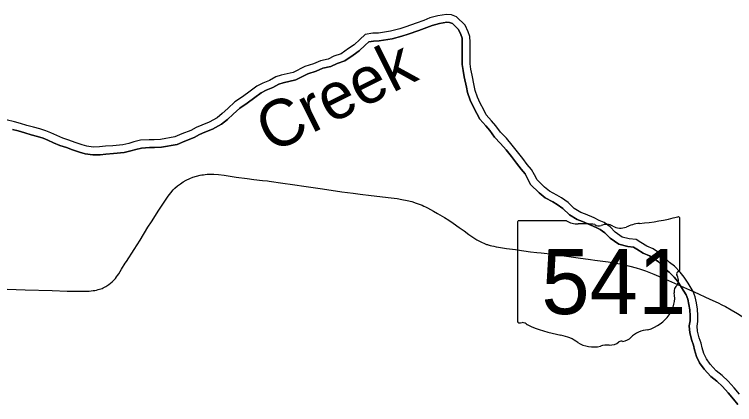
# Model space of a CAD drawing. Extents: x -29.6 to 34, y 0 to 22.
# Drawn here: x -24.702 to -23.331, y 11.058 to 11.8 of the extents above; entities that cross this region are included whole.
import ezdxf

# ---------------------------------------------------------------- set-up
doc = ezdxf.new("R2010")
doc.units = 0
for name, color, linetype in [('GM_X_County_Road', 7, 'Continuous'), ('GM_X_Major_River', 7, 'Continuous'), ('GM_X_Major_River_Text', 7, 'Continuous'), ('GM_X_State_Route', 7, 'Continuous'), ('GM_X_State_Shield', 7, 'Continuous')]:
    doc.layers.add(name, color=color, linetype=linetype)

msp = doc.modelspace()

# ---------------------------------------------------------------- linework, layer by layer
at = {"layer": 'GM_X_County_Road'}
for points in [[(-23.7078, 11.3472), (-23.6991, 11.3463), (-23.6771, 11.3437), (-23.6724, 11.3432)], [(-23.6724, 11.3432), (-23.6644, 11.3423), (-23.6376, 11.3385)], [(-23.6376, 11.3385), (-23.6287, 11.3372), (-23.6056, 11.3338), (-23.5973, 11.3326)], [(-23.5973, 11.3326), (-23.5722, 11.3292), (-23.5566, 11.3268), (-23.5435, 11.3242), (-23.5304, 11.3213), (-23.5185, 11.3182), (-23.5101, 11.3155), (-23.5008, 11.3122), (-23.4851, 11.3059), (-23.4719, 11.3003)], [(-23.4719, 11.3003), (-23.4631, 11.2965), (-23.4232, 11.2787), (-23.417, 11.2758), (-23.4086, 11.2721), (-23.3783, 11.2586), (-23.3627, 11.2513), (-23.3556, 11.2478)]]:
    msp.add_lwpolyline(points, dxfattribs=at)
at = {"layer": 'GM_X_Major_River'}
for points in [[(-23.8088, 11.6188), (-23.8157, 11.6316), (-23.8207, 11.6426), (-23.8251, 11.6553), (-23.8269, 11.6649), (-23.831, 11.6844), (-23.8332, 11.6958), (-23.8347, 11.7061), (-23.8348, 11.716), (-23.8345, 11.7267), (-23.8347, 11.7477), (-23.8352, 11.758), (-23.8384, 11.7672), (-23.8439, 11.78), (-23.8603, 11.7958), (-23.8703, 11.7993), (-23.8795, 11.8003), (-23.8962, 11.7973), (-23.9114, 11.7937), (-23.9224, 11.789), (-23.9373, 11.7835), (-23.9571, 11.7766), (-23.9684, 11.773), (-23.9858, 11.7682), (-24.0092, 11.7648), (-24.0198, 11.7644), (-24.034, 11.7621), (-24.0442, 11.7528), (-24.0551, 11.7424), (-24.0657, 11.7352), (-24.0799, 11.7255), (-24.0937, 11.7208), (-24.1046, 11.715), (-24.1192, 11.7121), (-24.1326, 11.7063), (-24.1489, 11.7012), (-24.1715, 11.69), (-24.1942, 11.6845), (-24.2041, 11.6812), (-24.2165, 11.6747), (-24.2289, 11.6693), (-24.2402, 11.6635), (-24.2529, 11.6541), (-24.2674, 11.6437), (-24.2822, 11.6337), (-24.2956, 11.6211), (-24.3061, 11.6114), (-24.3157, 11.6035), (-24.3309, 11.5952), (-24.345, 11.5898), (-24.356, 11.5851), (-24.3659, 11.5793), (-24.3829, 11.5728), (-24.3963, 11.567), (-24.4236, 11.5622), (-24.4357, 11.5617), (-24.4453, 11.5616), (-24.4619, 11.5608), (-24.4747, 11.5575), (-24.4839, 11.5549), (-24.4956, 11.552), (-24.5144, 11.5501), (-24.5286, 11.5493), (-24.5396, 11.5481), (-24.5517, 11.5477), (-24.5641, 11.5493), (-24.573, 11.5521), (-24.5862, 11.5566), (-24.5979, 11.5608), (-24.6097, 11.5646), (-24.6211, 11.5695), (-24.6321, 11.5748), (-24.6417, 11.5786), (-24.6535, 11.5825), (-24.6656, 11.5856), (-24.6777, 11.589), (-24.6901, 11.5928), (-24.7015, 11.596), (-24.7172, 11.5997)], [(-23.8219, 11.6118), (-23.829, 11.6249), (-23.8346, 11.637), (-23.8395, 11.6515), (-23.8415, 11.662), (-23.8456, 11.6815), (-23.8479, 11.6933), (-23.8496, 11.705), (-23.8497, 11.7162), (-23.8494, 11.7268), (-23.8496, 11.7473), (-23.8499, 11.7551), (-23.8523, 11.7618), (-23.8564, 11.7714), (-23.8683, 11.7829), (-23.8736, 11.7847), (-23.879, 11.7853), (-23.8931, 11.7828), (-23.9067, 11.7795), (-23.9169, 11.7751), (-23.9322, 11.7695), (-23.9524, 11.7625), (-23.9642, 11.7587), (-23.9827, 11.7536), (-24.0078, 11.75), (-24.0183, 11.7496), (-24.0273, 11.7481), (-24.0341, 11.7419), (-24.0458, 11.7308), (-24.0573, 11.723), (-24.0731, 11.7121), (-24.0877, 11.7071), (-24.0996, 11.7009), (-24.1147, 11.6978), (-24.1274, 11.6923), (-24.1433, 11.6873), (-24.1664, 11.6759), (-24.1901, 11.6702), (-24.1983, 11.6674), (-24.21, 11.6613), (-24.2225, 11.6558), (-24.2323, 11.6508), (-24.2441, 11.6421), (-24.2588, 11.6315), (-24.2729, 11.622), (-24.2855, 11.6102), (-24.2964, 11.6002), (-24.3073, 11.5912), (-24.3246, 11.5817), (-24.3394, 11.576), (-24.3493, 11.5718), (-24.3594, 11.5659), (-24.3773, 11.559), (-24.392, 11.5526), (-24.422, 11.5473), (-24.4354, 11.5468), (-24.4448, 11.5468), (-24.4597, 11.546), (-24.4708, 11.5431), (-24.4801, 11.5406), (-24.493, 11.5373), (-24.5132, 11.5353), (-24.5274, 11.5344), (-24.5385, 11.5333), (-24.5524, 11.5328), (-24.5673, 11.5348), (-24.5776, 11.538), (-24.5911, 11.5426), (-24.6027, 11.5467), (-24.6149, 11.5507), (-24.6272, 11.556), (-24.6381, 11.5611), (-24.6468, 11.5646), (-24.6576, 11.5682), (-24.6695, 11.5712), (-24.6819, 11.5748), (-24.6943, 11.5785), (-24.7052, 11.5815)], [(-24.7052, 11.5815), (-24.6943, 11.5785), (-24.6819, 11.5748), (-24.6695, 11.5712), (-24.6576, 11.5682), (-24.6468, 11.5646), (-24.6381, 11.5611), (-24.6272, 11.556), (-24.6149, 11.5507), (-24.6027, 11.5467), (-24.5911, 11.5426), (-24.5776, 11.538), (-24.5673, 11.5348), (-24.5524, 11.5328), (-24.5385, 11.5333), (-24.5274, 11.5344), (-24.5132, 11.5353), (-24.493, 11.5373), (-24.4801, 11.5406), (-24.4708, 11.5431), (-24.4597, 11.546), (-24.4448, 11.5468), (-24.4354, 11.5468), (-24.422, 11.5473), (-24.392, 11.5526), (-24.3773, 11.559), (-24.3594, 11.5659), (-24.3493, 11.5718), (-24.3394, 11.576), (-24.3246, 11.5817), (-24.3073, 11.5912), (-24.2964, 11.6002), (-24.2855, 11.6102), (-24.2729, 11.622), (-24.2588, 11.6315), (-24.2441, 11.6421), (-24.2323, 11.6508), (-24.2225, 11.6558), (-24.21, 11.6613), (-24.1983, 11.6674), (-24.1901, 11.6702), (-24.1664, 11.6759), (-24.1433, 11.6873), (-24.1274, 11.6923), (-24.1147, 11.6978), (-24.0996, 11.7009), (-24.0877, 11.7071), (-24.0731, 11.7121), (-24.0573, 11.723), (-24.0458, 11.7308), (-24.0341, 11.7419), (-24.0273, 11.7481), (-24.0183, 11.7496), (-24.0078, 11.75), (-23.9827, 11.7536), (-23.9642, 11.7587), (-23.9524, 11.7625), (-23.9322, 11.7695), (-23.9169, 11.7751), (-23.9067, 11.7795), (-23.8931, 11.7828), (-23.879, 11.7853), (-23.8736, 11.7847), (-23.8683, 11.7829), (-23.8564, 11.7714), (-23.8523, 11.7618), (-23.8499, 11.7551), (-23.8496, 11.7473), (-23.8494, 11.7268), (-23.8497, 11.7162), (-23.8496, 11.705), (-23.8479, 11.6933), (-23.8456, 11.6815), (-23.8415, 11.662), (-23.8395, 11.6515), (-23.8346, 11.637), (-23.829, 11.6249), (-23.822, 11.6119)], [(-23.3253, 11.0576), (-23.3336, 11.0679), (-23.3433, 11.0799), (-23.3544, 11.0919), (-23.365, 11.102), (-23.3769, 11.1111), (-23.3895, 11.1251), (-23.3979, 11.1372), (-23.4036, 11.1492), (-23.4074, 11.1617), (-23.4095, 11.1707), (-23.4127, 11.1799), (-23.4168, 11.1945), (-23.4179, 11.2075), (-23.4161, 11.2173), (-23.4162, 11.2267), (-23.4166, 11.2377), (-23.4182, 11.2484), (-23.4205, 11.2583), (-23.4236, 11.2666), (-23.4325, 11.2808), (-23.4396, 11.2918), (-23.4462, 11.3001), (-23.4556, 11.3097), (-23.465, 11.3169), (-23.4764, 11.3291), (-23.4845, 11.3351), (-23.4935, 11.3408), (-23.5056, 11.3461), (-23.5176, 11.3537), (-23.5235, 11.3574), (-23.5347, 11.3585), (-23.5514, 11.3629), (-23.5684, 11.3743), (-23.5783, 11.3845), (-23.587, 11.3911), (-23.5949, 11.3944), (-23.605, 11.3993), (-23.6208, 11.406), (-23.6306, 11.4099), (-23.6457, 11.4188), (-23.6579, 11.4309), (-23.6689, 11.4386), (-23.677, 11.4434), (-23.6919, 11.4512), (-23.7033, 11.4604), (-23.7194, 11.4767), (-23.7254, 11.4881), (-23.7301, 11.4966), (-23.7376, 11.5057), (-23.7461, 11.5169), (-23.756, 11.5298), (-23.7658, 11.5423), (-23.7765, 11.5548), (-23.7879, 11.5668), (-23.7971, 11.5791), (-23.8049, 11.5882), (-23.8161, 11.6007), (-23.822, 11.6119)], [(-23.822, 11.6119), (-23.8161, 11.6007), (-23.8049, 11.5882), (-23.7971, 11.5791), (-23.7879, 11.5668), (-23.7765, 11.5548), (-23.7658, 11.5423), (-23.756, 11.5298), (-23.7461, 11.5169), (-23.7376, 11.5057), (-23.7301, 11.4966), (-23.7254, 11.4881), (-23.7194, 11.4767), (-23.7033, 11.4604), (-23.6919, 11.4512), (-23.677, 11.4434), (-23.6689, 11.4386), (-23.6579, 11.4309), (-23.6457, 11.4188), (-23.6306, 11.4099), (-23.6208, 11.406), (-23.605, 11.3993), (-23.5949, 11.3944), (-23.587, 11.3911), (-23.5783, 11.3845), (-23.5684, 11.3743), (-23.5514, 11.3629), (-23.5347, 11.3585), (-23.5235, 11.3574), (-23.5176, 11.3537), (-23.5056, 11.3461), (-23.4935, 11.3408), (-23.4845, 11.3351), (-23.4764, 11.3291), (-23.465, 11.3169), (-23.4556, 11.3097), (-23.4462, 11.3001), (-23.4396, 11.2918), (-23.4325, 11.2808), (-23.4236, 11.2666), (-23.4205, 11.2583), (-23.4182, 11.2484), (-23.4166, 11.2377), (-23.4162, 11.2267), (-23.4161, 11.2173), (-23.4179, 11.2075), (-23.4168, 11.1945), (-23.4127, 11.1799), (-23.4095, 11.1707), (-23.4074, 11.1617), (-23.4036, 11.1492), (-23.3979, 11.1372), (-23.3895, 11.1251), (-23.3769, 11.1111), (-23.365, 11.102), (-23.3544, 11.0919), (-23.3433, 11.0799), (-23.3336, 11.0679), (-23.3253, 11.0576)], [(-23.322, 11.0773), (-23.332, 11.0896), (-23.3438, 11.1023), (-23.3553, 11.1133), (-23.3667, 11.1221), (-23.3778, 11.1344), (-23.385, 11.1447), (-23.3897, 11.1546), (-23.393, 11.1656), (-23.3952, 11.1748), (-23.3985, 11.1844), (-23.4021, 11.1972), (-23.4029, 11.2068), (-23.4012, 11.216), (-23.4013, 11.227), (-23.4017, 11.2391), (-23.4036, 11.2512), (-23.4062, 11.2626), (-23.4102, 11.2732), (-23.4199, 11.2888), (-23.4274, 11.3004), (-23.435, 11.31), (-23.4457, 11.3209), (-23.455, 11.3279), (-23.4665, 11.3403), (-23.4761, 11.3473), (-23.4864, 11.354), (-23.4986, 11.3592), (-23.5096, 11.3663), (-23.5185, 11.3719), (-23.532, 11.3732), (-23.5452, 11.3766), (-23.5588, 11.3858), (-23.5684, 11.3957), (-23.5795, 11.4041), (-23.5888, 11.4079), (-23.5988, 11.4128), (-23.6151, 11.4198), (-23.624, 11.4233), (-23.6365, 11.4307), (-23.6483, 11.4423), (-23.6608, 11.4511), (-23.6698, 11.4564), (-23.6837, 11.4637), (-23.6933, 11.4715), (-23.7073, 11.4856), (-23.7123, 11.4951), (-23.7177, 11.5051), (-23.726, 11.5149), (-23.7342, 11.5259), (-23.7443, 11.539), (-23.7543, 11.5517), (-23.7654, 11.5648), (-23.7765, 11.5764), (-23.7855, 11.5884), (-23.7937, 11.598), (-23.8038, 11.6093), (-23.8088, 11.6188)]]:
    msp.add_lwpolyline(points, dxfattribs=at)
at = {"layer": 'GM_X_State_Route'}
for points in [[(-24.7329, 11.278), (-24.6811, 11.2761), (-24.6298, 11.2746), (-24.6013, 11.2737), (-24.5833, 11.2734), (-24.5693, 11.2735), (-24.5595, 11.2738), (-24.552, 11.2745), (-24.5486, 11.275), (-24.5452, 11.2757), (-24.5424, 11.2764), (-24.5397, 11.2772), (-24.5374, 11.278), (-24.5348, 11.2789), (-24.5325, 11.2799), (-24.5301, 11.281), (-24.528, 11.2822), (-24.5256, 11.2835), (-24.5237, 11.2847), (-24.5218, 11.2861), (-24.5186, 11.2885), (-24.5156, 11.2912), (-24.5135, 11.2932), (-24.5116, 11.2953), (-24.5095, 11.2977), (-24.5073, 11.3007), (-24.5052, 11.3035), (-24.5032, 11.3063), (-24.4977, 11.3151), (-24.4907, 11.3266), (-24.4886, 11.3299), (-24.4736, 11.353), (-24.4625, 11.3708), (-24.4476, 11.3951), (-24.4411, 11.4054), (-24.4269, 11.4275), (-24.4155, 11.4451), (-24.4093, 11.4543), (-24.4043, 11.4609), (-24.3997, 11.4661), (-24.3964, 11.4695), (-24.3915, 11.4737), (-24.3859, 11.478), (-24.3805, 11.4815), (-24.3748, 11.4846), (-24.3679, 11.4879), (-24.3619, 11.4902), (-24.3552, 11.4924), (-24.3483, 11.4941), (-24.3453, 11.4947), (-24.342, 11.4952), (-24.3386, 11.4957), (-24.335, 11.496), (-24.3312, 11.4962), (-24.3273, 11.4963), (-24.3221, 11.4962), (-24.3133, 11.4956), (-24.3023, 11.4942), (-24.2798, 11.4907), (-24.2585, 11.4878), (-24.2458, 11.4863), (-24.2296, 11.4844), (-24.2198, 11.4833), (-24.2169, 11.4829), (-24.191, 11.4793), (-24.1726, 11.4765), (-24.1467, 11.4727), (-24.1201, 11.469), (-24.0989, 11.4658), (-24.0787, 11.4629), (-24.0573, 11.4601), (-24.0435, 11.4581), (-24.0227, 11.4556), (-23.9845, 11.4512), (-23.9735, 11.4497), (-23.9643, 11.4482), (-23.9546, 11.4462), (-23.9455, 11.4439), (-23.9372, 11.4413), (-23.9335, 11.44), (-23.9295, 11.4385), (-23.9261, 11.4371)], [(-23.9261, 11.4371), (-23.9226, 11.4355), (-23.9192, 11.4339), (-23.9158, 11.4321), (-23.9045, 11.4258), (-23.8964, 11.4213)], [(-23.8964, 11.4213), (-23.8924, 11.4191), (-23.8834, 11.4138), (-23.875, 11.4085), (-23.8668, 11.403), (-23.8554, 11.3948), (-23.8462, 11.3882)], [(-23.8462, 11.3882), (-23.837, 11.3816), (-23.8274, 11.375), (-23.8215, 11.3714), (-23.8178, 11.3693), (-23.8139, 11.3672), (-23.8114, 11.366), (-23.8087, 11.3648), (-23.8061, 11.3636), (-23.8033, 11.3626), (-23.8017, 11.3621)], [(-23.8017, 11.3621), (-23.8002, 11.3616), (-23.7967, 11.3607), (-23.7931, 11.3597), (-23.7894, 11.3589), (-23.7851, 11.3579), (-23.7803, 11.3572), (-23.7654, 11.3549), (-23.7481, 11.3526), (-23.7448, 11.3521), (-23.7326, 11.3503), (-23.7199, 11.3485), (-23.7078, 11.3472)], [(-23.7078, 11.3472), (-23.6991, 11.3463), (-23.6771, 11.3437), (-23.6724, 11.3432)], [(-23.6724, 11.3432), (-23.6644, 11.3423), (-23.6376, 11.3385)], [(-23.6376, 11.3385), (-23.6287, 11.3372), (-23.6056, 11.3338), (-23.5973, 11.3326)], [(-23.5973, 11.3326), (-23.5722, 11.3292), (-23.5566, 11.3268), (-23.5435, 11.3242), (-23.5304, 11.3213), (-23.5185, 11.3182), (-23.5101, 11.3155), (-23.5008, 11.3122), (-23.4851, 11.3059), (-23.4719, 11.3003)], [(-23.4719, 11.3003), (-23.4631, 11.2965), (-23.4232, 11.2787), (-23.417, 11.2758), (-23.4086, 11.2721), (-23.3783, 11.2586), (-23.3627, 11.2513), (-23.3556, 11.2478)], [(-23.3556, 11.2478), (-23.3489, 11.2444), (-23.3376, 11.2382), (-23.3256, 11.231), (-23.3118, 11.2222), (-23.2935, 11.2098), (-23.2673, 11.1916)]]:
    msp.add_lwpolyline(points, dxfattribs=at)
at = {"layer": 'GM_X_State_Shield'}
for p, q in [((-23.7447, 11.4043), (-23.7447, 11.2166)), ((-23.6511, 11.4075), (-23.7416, 11.4075)), ((-23.4357, 11.314), (-23.4357, 11.4121)), ((-23.4357, 11.314), (-23.4357, 11.314))]:
    msp.add_line(p, q, dxfattribs=at)
for centre, major_axis, start_param, end_param in [((-23.5457, 11.6633), (0.3277, 0), 4.814394, 5.042369), ((-23.4391, 11.4125), (0.00344, 0), 6.141152, 7.989035), ((-23.7411, 11.4047), (0.00358, 0), 1.712693, 3.28349), ((-23.6296, 11.4293), (0.0347, 0), 4.042523, 4.731795), ((-23.6181, 11.3022), (0.1246, 0), 1.404758, 1.657858), ((-23.5751, 11.3839), (0.0208, 0), 0.950623, 2.079405), ((-23.504, 11.3502), (0.0659, 0), 1.699011, 2.107814), ((-23.5898, 11.4056), (0.01, 0), 3.836095, 5.185415), ((-23.5482, 11.4137), (0.0251, 0), 4.081561, 5.145723), ((-23.4365, 11.3068), (0.00532, 0), 1.883978, 3.671073), ((-23.4703, 11.2944), (0.032, 0), 5.934695, 6.695948), ((-23.4394, 11.3136), (0.00368, 0), 5.05454, 6.418171), ((-23.4234, 11.2729), (0.0232, 0), 2.387724, 3.262537), ((-23.5274, 11.2604), (0.082, 0), 5.101752, 6.440018), ((-23.7411, 11.2162), (0.00361, 0), 3.00124, 4.508301), ((-23.7405, 11.2354), (0.0276, 0), 4.665946, 4.897461), ((-23.7349, 11.2058), (0.00994, 0), 0.519207, 1.627899), ((-23.6094, 11.3744), (0.2366, 0), 4.195997, 4.488961), ((-23.4928, 11.164), (0.0449, 0), 1.647645, 2.488434), ((-23.68, 11.1324), (0.074, 0), 0.823519, 1.323587), ((-23.5497, 11.1985), (0.0265, 0), 4.937069, 5.64225), ((-23.5999, 11.2049), (0.047, 0), 4.026481, 4.996735), ((-23.5728, 11.14), (0.0386, 0), 1.495662, 1.94098), ((-23.5693, 11.1908), (0.025, 0), 4.691044, 5.507374), ((-23.5467, 11.1727), (0.00705, 0), 1.147584, 2.315152)]:
    msp.add_ellipse(centre, major_axis=major_axis, ratio=0.8, start_param=start_param, end_param=end_param, dxfattribs=at)

# ---------------------------------------------------------------- texts
at = {"layer": 'GM_X_Major_River_Text'}
msp.add_text('Creek', height=0.08877, rotation=26.6433, dxfattribs=at).set_placement((-24.2126, 11.535))
at = {"layer": 'GM_X_State_Shield'}
msp.add_text('541', height=0.1236, dxfattribs=at).set_placement((-23.6991, 11.2299))

doc.saveas('drawing.dxf')
